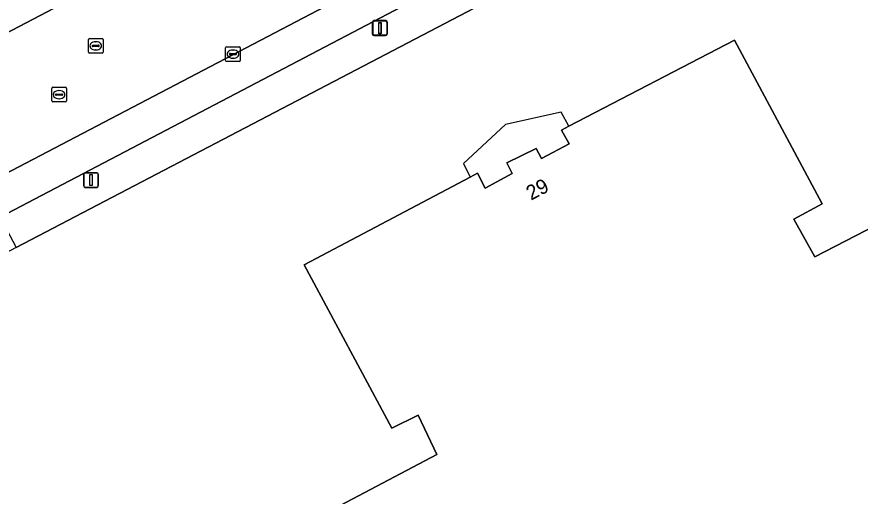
# Model space of a CAD drawing. Extents: x 157692 to 159674, y 381452 to 383291.
# Drawn here: x 158408.1 to 158465.6, y 381857.2 to 381889.9 of the extents above; entities that cross this region are included whole.
import ezdxf

# ---------------------------------------------------------------- set-up
doc = ezdxf.new("R2010")
doc.units = 0
for name, color, linetype in [('IMGEO_Erf', 7, 'Continuous'), ('IMGEO_Kolk', 7, 'Continuous'), ('IMGEO_Lichtmast', 7, 'Continuous'), ('IMGEO_Pand', 7, 'Continuous'), ('IMGEO_Pand_nummerreeks', 7, 'Continuous'), ('IMGEO_Pand_overbouw', 7, 'Continuous'), ('IMGEO_Parkeervlak_open', 7, 'Continuous'), ('IMGEO_Rijbaan_lokaal_gesloten', 7, 'Continuous'), ('IMGEO_Rioolput', 7, 'Continuous'), ('IMGEO_Voetpad_open', 7, 'Continuous')]:
    doc.layers.add(name, color=color, linetype=linetype)

msp = doc.modelspace()

# ---------------------------------------------------------------- linework, layer by layer
at = {"layer": 'IMGEO_Erf'}
for points in [[(158416.142, 381764.387), (158441.975, 381777.745), (158461.034, 381788.171), (158500, 381809.488), (158502.7, 381810.965), (158517.225, 381818.911), (158502.7, 381848.284), (158500, 381853.744), (158473.086, 381908.164), (158468.009, 381905.516), (158408.054, 381874.141), (158402.221, 381871.049), (158376.84, 381857.708), (158371.263, 381854.776), (158369.169, 381853.676), (158368.188, 381853.16), (158362.112, 381850.005), (158326.367, 381831.251), (158320.477, 381828.192), (158299.749, 381817.336), (158293.835, 381814.232), (158289.45, 381811.892), (158283.086, 381808.549)], [(158469.028, 381805.901), (158462.391, 381818.606), (158444.04, 381808.991), (158423.833, 381847.573), (158421.513, 381852.002), (158436.722, 381860.027), (158435.442, 381862.688), (158433.661, 381861.806), (158427.69, 381872.962), (158438.993, 381878.936), (158439.486, 381879.197), (158440.018, 381878.184), (158441.862, 381879.176), (158441.494, 381879.914), (158443.493, 381880.877), (158443.857, 381880.213), (158445.739, 381881.199), (158445.21, 381882.131), (158445.724, 381882.398), (158457.019, 381888.266), (158462.982, 381877.104), (158461.052, 381876.066), (158462.48, 381873.488), (158478.602, 381881.811)]]:
    msp.add_lwpolyline(points, dxfattribs=at)
at = {"layer": 'IMGEO_Kolk'}
for p, q in [((158422.327, 381886.896), (158422.327, 381887.748)), ((158422.402, 381887.822), (158423.254, 381887.822)), ((158422.815, 381887.602), (158422.84, 381887.602)), ((158423.328, 381887.748), (158423.328, 381886.896)), ((158422.586, 381887.316), (158422.586, 381887.328)), ((158423.024, 381887.279), (158422.626, 381887.279)), ((158422.629, 381887.365), (158423.027, 381887.365)), ((158422.838, 381887.042), (158422.813, 381887.042)), ((158423.07, 381887.328), (158423.07, 381887.316)), ((158423.254, 381886.822), (158422.402, 381886.822))]:
    msp.add_line(p, q, dxfattribs=at)
for points in [[(158422.327, 381886.896), (158422.327, 381887.748)], [(158422.402, 381887.822), (158423.254, 381887.822)], [(158423.328, 381887.748), (158423.328, 381886.896)], [(158423.254, 381886.822), (158422.402, 381886.822)]]:
    msp.add_lwpolyline(points, dxfattribs=at)
for centre, radius, start, end in [((158422.404, 381887.746), 0.0765, 91.55205, 178.44795), ((158422.404, 381887.746), 0.0765, 91.55205, 178.44795), ((158423.252, 381887.746), 0.0765, 1.55205, 88.44795), ((158423.252, 381887.746), 0.0765, 1.55205, 88.44795), ((158422.404, 381886.898), 0.0765, 181.55205, 268.44795), ((158422.404, 381886.898), 0.0765, 181.55205, 268.44795), ((158422.626, 381887.325), 0.0403, 85.87752, 175.75265), ((158422.623, 381887.315), 0.0366, 178.93798, 274.71019), ((158423.027, 381887.322), 0.043, 264.86636, 352.45326), ((158423.031, 381887.327), 0.0386, 1.73085, 96.63898), ((158423.252, 381886.898), 0.0765, 271.55205, 358.44795), ((158423.252, 381886.898), 0.0765, 271.55205, 358.44795)]:
    msp.add_arc(centre, radius, start, end, dxfattribs=at)
for centre, major_axis, ratio, start_param, end_param in [((158422.814, 381887.322), (-0.387, 0.002), 0.722429, 4.712389, 7.853982), ((158422.839, 381887.322), (-0.39, 0.002), 0.717154, 1.570796, 4.712389)]:
    msp.add_ellipse(centre, major_axis=major_axis, ratio=ratio, start_param=start_param, end_param=end_param, dxfattribs=at)
at = {"layer": 'IMGEO_Lichtmast'}
for p, q in [((158432.338, 381888.683), (158432.338, 381889.483)), ((158432.338, 381889.483), (158432.338, 381888.683)), ((158432.349, 381888.709), (158432.349, 381889.509)), ((158432.349, 381889.509), (158432.349, 381888.709)), ((158432.438, 381889.583), (158433.228, 381889.583)), ((158433.228, 381889.583), (158432.438, 381889.583)), ((158432.449, 381889.609), (158433.239, 381889.609)), ((158433.239, 381889.609), (158432.449, 381889.609)), ((158433.328, 381889.483), (158433.328, 381888.683)), ((158433.328, 381888.683), (158433.328, 381889.483)), ((158433.339, 381889.509), (158433.339, 381888.709)), ((158433.339, 381888.709), (158433.339, 381889.509)), ((158433.228, 381888.583), (158432.438, 381888.583)), ((158432.438, 381888.583), (158433.228, 381888.583)), ((158433.239, 381888.609), (158432.449, 381888.609)), ((158432.449, 381888.609), (158433.239, 381888.609)), ((158412.659, 381878.334), (158412.659, 381879.134)), ((158412.659, 381879.134), (158412.659, 381878.334)), ((158412.759, 381879.234), (158413.549, 381879.234)), ((158413.549, 381879.234), (158412.759, 381879.234)), ((158413.649, 381879.134), (158413.649, 381878.334)), ((158413.649, 381878.334), (158413.649, 381879.134)), ((158413.549, 381878.234), (158412.759, 381878.234)), ((158412.759, 381878.234), (158413.549, 381878.234))]:
    msp.add_line(p, q, dxfattribs=at)
for points in [[(158432.758, 381889.458), (158432.908, 381889.458), (158432.908, 381888.708), (158432.758, 381888.708), (158432.758, 381889.458)], [(158432.769, 381889.484), (158432.919, 381889.484), (158432.919, 381888.734), (158432.769, 381888.734), (158432.769, 381889.484)], [(158413.079, 381879.109), (158413.229, 381879.109), (158413.229, 381878.359), (158413.079, 381878.359), (158413.079, 381879.109)]]:
    msp.add_lwpolyline(points, dxfattribs=at)
for centre, start, end in [((158432.438, 381889.483), 90, 180), ((158432.438, 381889.483), 90, 180), ((158432.449, 381889.509), 90, 180), ((158432.449, 381889.509), 90, 180), ((158433.228, 381889.483), 0, 90), ((158433.228, 381889.483), 360, 90), ((158433.239, 381889.509), 0, 90), ((158433.239, 381889.509), 360, 90), ((158432.438, 381888.683), 180, 270), ((158432.438, 381888.683), 180, 270), ((158432.449, 381888.709), 180, 270), ((158432.449, 381888.709), 180, 270), ((158433.228, 381888.683), 270, 0), ((158433.228, 381888.683), 270, 0), ((158433.239, 381888.709), 270, 0), ((158433.239, 381888.709), 270, 0), ((158412.759, 381879.134), 90, 180), ((158412.759, 381879.134), 90, 180), ((158413.549, 381879.134), 0, 90), ((158413.549, 381879.134), 360, 90), ((158412.759, 381878.334), 180, 270), ((158412.759, 381878.334), 180, 270), ((158413.549, 381878.334), 270, 0), ((158413.549, 381878.334), 270, 0)]:
    msp.add_arc(centre, 0.1, start, end, dxfattribs=at)
at = {"layer": 'IMGEO_Pand'}
msp.add_lwpolyline([(158478.602, 381881.811), (158462.48, 381873.488), (158461.052, 381876.066), (158462.982, 381877.104), (158457.019, 381888.266), (158445.724, 381882.398), (158445.21, 381882.131), (158445.739, 381881.199), (158443.857, 381880.213), (158443.493, 381880.877), (158441.494, 381879.914), (158441.862, 381879.176), (158440.018, 381878.184), (158439.486, 381879.197), (158438.993, 381878.936), (158427.69, 381872.962), (158433.661, 381861.806), (158435.442, 381862.688), (158436.722, 381860.027), (158421.513, 381852.002), (158423.833, 381847.573), (158444.04, 381808.991), (158462.391, 381818.606), (158469.028, 381805.901)], dxfattribs=at)
at = {"layer": 'IMGEO_Pand_overbouw'}
msp.add_lwpolyline([(158445.724, 381882.398), (158445.204, 381883.368), (158441.392, 381882.532), (158438.537, 381879.872), (158438.993, 381878.936), (158439.486, 381879.197), (158440.018, 381878.184), (158441.862, 381879.176), (158441.494, 381879.914), (158443.493, 381880.877), (158443.857, 381880.213), (158445.739, 381881.199), (158445.21, 381882.131)], close=True, dxfattribs=at)
at = {"layer": 'IMGEO_Parkeervlak_open'}
for points in [[(158275.635, 381819.726), (158303.732, 381834.411), (158354.339, 381860.942), (158456.473, 381914.515)], [(158465.398, 381909.602), (158462.964, 381908.32), (158340.401, 381844.12), (158287.161, 381816.195)], [(158292.185, 381815.989), (158292.781, 381816.313), (158298.654, 381819.389), (158319.401, 381830.234), (158325.276, 381833.312), (158361.043, 381852.051), (158367.101, 381855.247), (158370.176, 381856.864), (158375.752, 381859.796), (158401.117, 381873.133), (158406.97, 381876.204), (158463.062, 381905.633)]]:
    msp.add_lwpolyline(points, dxfattribs=at)
at = {"layer": 'IMGEO_Rijbaan_lokaal_gesloten'}
for points in [[(158462.964, 381908.32), (158465.398, 381909.602), (158465.751, 381909.788), (158471.08, 381912.561), (158472.817, 381913.475), (158469.812, 381921.671), (158469.469, 381921.453), (158467.76, 381920.403), (158467.185, 381920.095), (158464.206, 381918.501), (158463.074, 381917.968), (158462.356, 381917.596), (158458.149, 381915.386), (158456.473, 381914.515), (158354.339, 381860.942), (158303.732, 381834.411), (158275.635, 381819.726)], [(158280.869, 381812.874), (158287.161, 381816.195), (158340.401, 381844.12), (158462.964, 381908.32)]]:
    msp.add_lwpolyline(points, dxfattribs=at)
at = {"layer": 'IMGEO_Rioolput'}
for p, q in [((158412.973, 381887.459), (158412.973, 381888.311)), ((158413.048, 381888.385), (158413.9, 381888.385)), ((158413.461, 381888.165), (158413.486, 381888.165)), ((158413.974, 381888.311), (158413.974, 381887.459)), ((158413.232, 381887.879), (158413.232, 381887.891)), ((158413.67, 381887.842), (158413.272, 381887.842)), ((158413.275, 381887.928), (158413.673, 381887.928)), ((158413.484, 381887.605), (158413.459, 381887.605)), ((158413.716, 381887.891), (158413.716, 381887.879)), ((158413.9, 381887.385), (158413.048, 381887.385)), ((158410.473, 381884.132), (158410.473, 381884.984)), ((158410.548, 381885.058), (158411.4, 381885.058)), ((158410.732, 381884.552), (158410.732, 381884.564)), ((158410.775, 381884.601), (158411.173, 381884.601)), ((158410.961, 381884.838), (158410.986, 381884.838)), ((158411.216, 381884.564), (158411.216, 381884.552)), ((158411.474, 381884.984), (158411.474, 381884.132)), ((158411.4, 381884.058), (158410.548, 381884.058)), ((158411.17, 381884.515), (158410.772, 381884.515)), ((158410.984, 381884.278), (158410.959, 381884.278))]:
    msp.add_line(p, q, dxfattribs=at)
for points in [[(158412.973, 381887.459), (158412.973, 381888.311)], [(158413.048, 381888.385), (158413.9, 381888.385)], [(158413.974, 381888.311), (158413.974, 381887.459)], [(158413.9, 381887.385), (158413.048, 381887.385)], [(158410.473, 381884.132), (158410.473, 381884.984)], [(158410.548, 381885.058), (158411.4, 381885.058)], [(158411.474, 381884.984), (158411.474, 381884.132)], [(158411.4, 381884.058), (158410.548, 381884.058)]]:
    msp.add_lwpolyline(points, dxfattribs=at)
for centre, radius, start, end in [((158413.05, 381888.309), 0.0765, 91.55205, 178.44795), ((158413.05, 381888.309), 0.0765, 91.55205, 178.44795), ((158413.898, 381888.309), 0.0765, 1.55205, 88.44795), ((158413.898, 381888.309), 0.0765, 1.55205, 88.44795), ((158413.05, 381887.461), 0.0765, 181.55205, 268.44795), ((158413.05, 381887.461), 0.0765, 181.55205, 268.44795), ((158413.272, 381887.888), 0.0403, 85.87752, 175.75265), ((158413.269, 381887.878), 0.0366, 178.93798, 274.71019), ((158413.673, 381887.885), 0.043, 264.86636, 352.45326), ((158413.677, 381887.89), 0.0386, 1.73085, 96.63898), ((158413.898, 381887.461), 0.0765, 271.55205, 358.44795), ((158413.898, 381887.461), 0.0765, 271.55205, 358.44795), ((158410.55, 381884.982), 0.0765, 91.55205, 178.44795), ((158410.55, 381884.982), 0.0765, 91.55205, 178.44795), ((158410.772, 381884.561), 0.0403, 85.87752, 175.75265), ((158410.769, 381884.551), 0.0366, 178.93798, 274.71019), ((158411.173, 381884.558), 0.043, 264.86636, 352.45326), ((158411.177, 381884.563), 0.0386, 1.73085, 96.63898), ((158411.398, 381884.982), 0.0765, 1.55205, 88.44795), ((158411.398, 381884.982), 0.0765, 1.55205, 88.44795), ((158410.55, 381884.134), 0.0765, 181.55205, 268.44795), ((158410.55, 381884.134), 0.0765, 181.55205, 268.44795), ((158411.398, 381884.134), 0.0765, 271.55205, 358.44795), ((158411.398, 381884.134), 0.0765, 271.55205, 358.44795)]:
    msp.add_arc(centre, radius, start, end, dxfattribs=at)
for centre, major_axis, ratio, start_param, end_param in [((158413.46, 381887.885), (-0.387, 0.002), 0.722429, 4.712389, 7.853982), ((158413.485, 381887.885), (-0.39, 0.002), 0.717154, 1.570796, 4.712389), ((158410.96, 381884.558), (-0.387, 0.002), 0.722429, 4.712389, 7.853982), ((158410.985, 381884.558), (-0.39, 0.002), 0.717154, 1.570796, 4.712389)]:
    msp.add_ellipse(centre, major_axis=major_axis, ratio=ratio, start_param=start_param, end_param=end_param, dxfattribs=at)
at = {"layer": 'IMGEO_Voetpad_open'}
msp.add_lwpolyline([(158463.062, 381905.633), (158406.97, 381876.204), (158408.054, 381874.141), (158468.009, 381905.516), (158465.751, 381909.788), (158465.398, 381909.602)], dxfattribs=at)

# ---------------------------------------------------------------- texts
at = {"layer": 'IMGEO_Pand_nummerreeks'}
msp.add_text('29', height=1, rotation=27.55575, dxfattribs=at).set_placement((158443.139, 381877.324))

doc.saveas('drawing.dxf')
